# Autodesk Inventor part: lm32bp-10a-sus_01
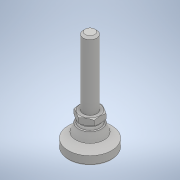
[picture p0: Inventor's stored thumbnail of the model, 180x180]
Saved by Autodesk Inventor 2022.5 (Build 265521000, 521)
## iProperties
Part Number: lm32bp-10a-sus_01
Material: 一般
Document SubType Name: Modeling
Designer: ImaoCorp
Density: 1 g/cm^3
Appearance: 既定
Author: ImaoCorp
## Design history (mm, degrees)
feature "lm32bp-10a-sus_01"
node "ソリッド1"
